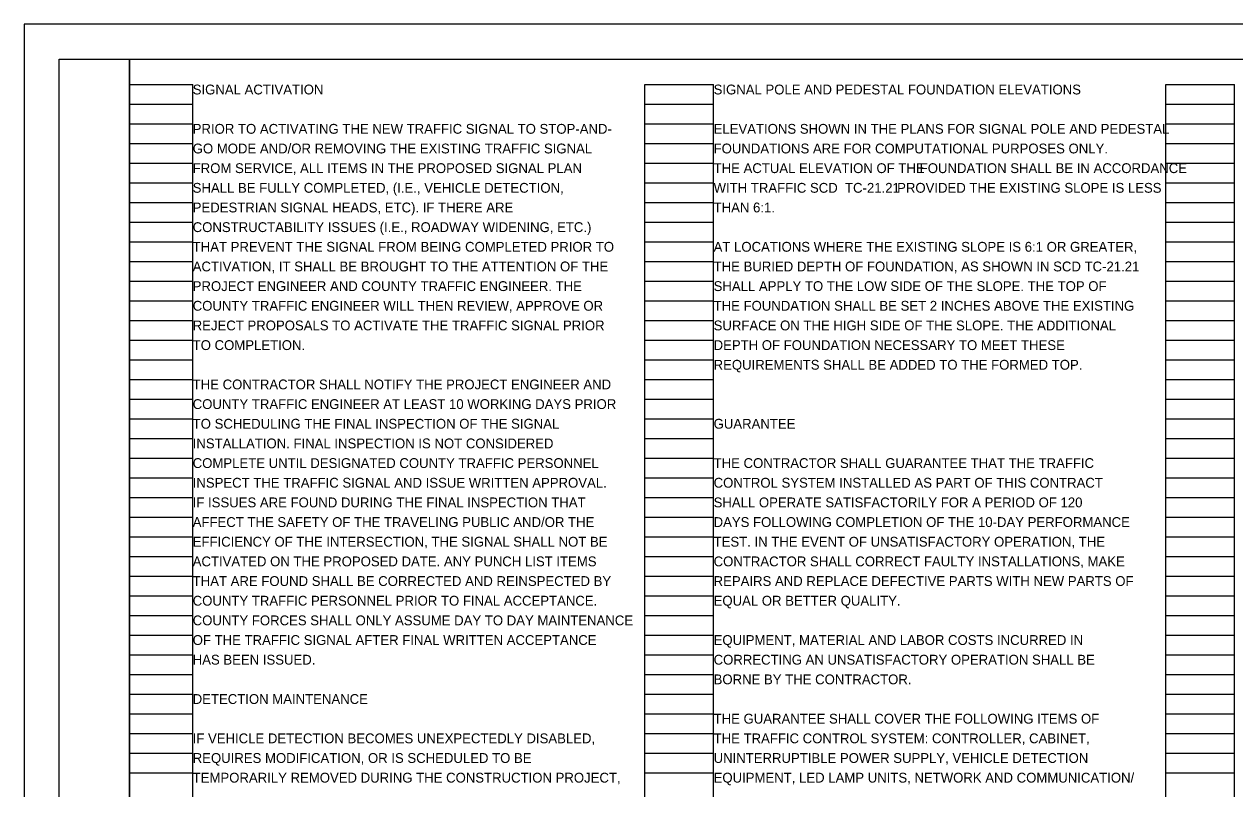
# Model space of a CAD drawing. Extents: x 0 to 34, y 0 to 22.
# Drawn here: x 0 to 17.24, y 11.11 to 22 of the extents above; entities that cross this region are included whole.
import ezdxf

# ---------------------------------------------------------------- set-up
doc = ezdxf.new("R2010")
doc.units = 0
for name, color, linetype in [('SH_Border', 7, 'Continuous'), ('SH_Cut_Line', 7, 'Continuous'), ('SH_Data', 7, 'Continuous'), ('SH_Text', 7, 'Continuous')]:
    doc.layers.add(name, color=color, linetype=linetype)

msp = doc.modelspace()

# ---------------------------------------------------------------- linework, layer by layer
at = {"layer": 'SH_Border'}
for points in [[(0.5, 21.5), (1.5, 21.5), (1.5, 0.5), (0.5, 0.5)], [(1.5, 21.5), (33.5, 21.5), (33.5, 0.5), (1.5, 0.5)]]:
    msp.add_lwpolyline(points, close=True, dxfattribs=at)
at = {"layer": 'SH_Cut_Line'}
msp.add_lwpolyline([(0, 0), (34, 0), (34, 22), (0, 22)], close=True, dxfattribs=at)
at = {"layer": 'SH_Data'}
for p, q in [((1.5, 0.98), (1.5, 21.14)), ((1.5, 21.14), (2.4, 21.14)), ((2.4, 0.98), (2.4, 21.14)), ((8.84, 0.98), (8.84, 21.14)), ((8.84, 21.14), (9.82, 21.14)), ((9.82, 0.98), (9.82, 21.14)), ((16.26, 0.98), (16.26, 21.14)), ((16.26, 21.14), (17.24, 21.14)), ((17.24, 0.98), (17.24, 21.14)), ((1.5, 20.86), (2.4, 20.86)), ((8.84, 20.86), (9.82, 20.86)), ((16.26, 20.86), (17.24, 20.86)), ((1.5, 20.58), (2.4, 20.58)), ((8.84, 20.58), (9.82, 20.58)), ((16.26, 20.58), (17.24, 20.58)), ((1.5, 20.3), (2.4, 20.3)), ((8.84, 20.3), (9.82, 20.3)), ((16.26, 20.3), (17.24, 20.3)), ((1.5, 20.02), (2.4, 20.02)), ((8.84, 20.02), (9.82, 20.02)), ((16.26, 20.02), (17.24, 20.02)), ((1.5, 19.74), (2.4, 19.74)), ((8.84, 19.74), (9.82, 19.74)), ((16.26, 19.74), (17.24, 19.74)), ((1.5, 19.46), (2.4, 19.46)), ((8.84, 19.46), (9.82, 19.46)), ((16.26, 19.46), (17.24, 19.46)), ((1.5, 19.18), (2.4, 19.18)), ((8.84, 19.18), (9.82, 19.18)), ((16.26, 19.18), (17.24, 19.18)), ((1.5, 18.9), (2.4, 18.9)), ((8.84, 18.9), (9.82, 18.9)), ((16.26, 18.9), (17.24, 18.9)), ((1.5, 18.62), (2.4, 18.62)), ((8.84, 18.62), (9.82, 18.62)), ((16.26, 18.62), (17.24, 18.62)), ((1.5, 18.34), (2.4, 18.34)), ((8.84, 18.34), (9.82, 18.34)), ((16.26, 18.34), (17.24, 18.34)), ((1.5, 18.06), (2.4, 18.06)), ((8.84, 18.06), (9.82, 18.06)), ((16.26, 18.06), (17.24, 18.06)), ((1.5, 17.78), (2.4, 17.78)), ((8.84, 17.78), (9.82, 17.78)), ((16.26, 17.78), (17.24, 17.78)), ((1.5, 17.5), (2.4, 17.5)), ((8.84, 17.5), (9.82, 17.5)), ((16.26, 17.5), (17.24, 17.5)), ((1.5, 17.22), (2.4, 17.22)), ((8.84, 17.22), (9.82, 17.22)), ((16.26, 17.22), (17.24, 17.22)), ((1.5, 16.94), (2.4, 16.94)), ((8.84, 16.94), (9.82, 16.94)), ((16.26, 16.94), (17.24, 16.94)), ((1.5, 16.66), (2.4, 16.66)), ((8.84, 16.66), (9.82, 16.66)), ((16.26, 16.66), (17.24, 16.66)), ((1.5, 16.38), (2.4, 16.38)), ((8.84, 16.38), (9.82, 16.38)), ((16.26, 16.38), (17.24, 16.38)), ((1.5, 16.1), (2.4, 16.1)), ((8.84, 16.1), (9.82, 16.1)), ((16.26, 16.1), (17.24, 16.1)), ((1.5, 15.82), (2.4, 15.82)), ((8.84, 15.82), (9.82, 15.82)), ((16.26, 15.82), (17.24, 15.82)), ((1.5, 15.54), (2.4, 15.54)), ((8.84, 15.54), (9.82, 15.54)), ((16.26, 15.54), (17.24, 15.54)), ((1.5, 15.26), (2.4, 15.26)), ((8.84, 15.26), (9.82, 15.26)), ((16.26, 15.26), (17.24, 15.26)), ((1.5, 14.98), (2.4, 14.98)), ((8.84, 14.98), (9.82, 14.98)), ((16.26, 14.98), (17.24, 14.98)), ((1.5, 14.7), (2.4, 14.7)), ((8.84, 14.7), (9.82, 14.7)), ((16.26, 14.7), (17.24, 14.7)), ((1.5, 14.42), (2.4, 14.42)), ((8.84, 14.42), (9.82, 14.42)), ((16.26, 14.42), (17.24, 14.42)), ((1.5, 14.14), (2.4, 14.14)), ((8.84, 14.14), (9.82, 14.14)), ((16.26, 14.14), (17.24, 14.14)), ((1.5, 13.86), (2.4, 13.86)), ((8.84, 13.86), (9.82, 13.86)), ((16.26, 13.86), (17.24, 13.86)), ((1.5, 13.58), (2.4, 13.58)), ((8.84, 13.58), (9.82, 13.58)), ((16.26, 13.58), (17.24, 13.58)), ((1.5, 13.3), (2.4, 13.3)), ((8.84, 13.3), (9.82, 13.3)), ((16.26, 13.3), (17.24, 13.3)), ((1.5, 13.02), (2.4, 13.02)), ((8.84, 13.02), (9.82, 13.02)), ((16.26, 13.02), (17.24, 13.02)), ((1.5, 12.74), (2.4, 12.74)), ((8.84, 12.74), (9.82, 12.74)), ((16.26, 12.74), (17.24, 12.74)), ((1.5, 12.46), (2.4, 12.46)), ((8.84, 12.46), (9.82, 12.46)), ((16.26, 12.46), (17.24, 12.46)), ((1.5, 12.18), (2.4, 12.18)), ((8.84, 12.18), (9.82, 12.18)), ((16.26, 12.18), (17.24, 12.18)), ((1.5, 11.9), (2.4, 11.9)), ((8.84, 11.9), (9.82, 11.9)), ((16.26, 11.9), (17.24, 11.9)), ((1.5, 11.62), (2.4, 11.62)), ((8.84, 11.62), (9.82, 11.62)), ((16.26, 11.62), (17.24, 11.62)), ((1.5, 11.34), (2.4, 11.34)), ((8.84, 11.34), (9.82, 11.34)), ((16.26, 11.34), (17.24, 11.34))]:
    msp.add_line(p, q, dxfattribs=at)

# ---------------------------------------------------------------- texts
at = {"layer": 'SH_Text'}
for s, p in [('SIGNAL ACTIVATION', (2.4, 21)), ('SIGNAL POLE AND PEDESTAL FOUNDATION ELEVATIONS', (9.82, 21)), ('PRIOR TO ACTIVATING THE NEW TRAFFIC SIGNAL TO STOP-AND-', (2.4, 20.44)), ('ELEVATIONS SHOWN IN THE PLANS FOR SIGNAL POLE AND PEDESTAL', (9.82, 20.44)), ('GO MODE AND/OR REMOVING THE EXISTING TRAFFIC SIGNAL', (2.4, 20.16)), ('FOUNDATIONS ARE FOR COMPUTATIONAL PURPOSES ONLY. ', (9.82, 20.16)), ('FROM SERVICE, ALL ITEMS IN THE PROPOSED SIGNAL PLAN', (2.4, 19.88)), ('THE ACTUAL ELEVATION OF THE  ', (9.82, 19.88)), ('FOUNDATION SHALL BE IN ACCORDANCE ', (12.756, 19.88)), ('SHALL BE FULLY COMPLETED, (I.E., VEHICLE DETECTION,', (2.4, 19.6)), ('WITH TRAFFIC SCD  TC-21.21 ', (9.82, 19.6)), ('PROVIDED THE EXISTING SLOPE IS LESS ', (12.434, 19.6)), ('PEDESTRIAN SIGNAL HEADS, ETC). IF THERE ARE', (2.4, 19.32)), ('THAN 6:1.', (9.82, 19.32)), ('CONSTRUCTABILITY ISSUES (I.E., ROADWAY WIDENING, ETC.)', (2.4, 19.04)), ('THAT PREVENT THE SIGNAL FROM BEING COMPLETED PRIOR TO', (2.4, 18.76)), ('AT LOCATIONS WHERE THE EXISTING SLOPE IS 6:1 OR GREATER,', (9.82, 18.76)), ('ACTIVATION, IT SHALL BE BROUGHT TO THE ATTENTION OF THE', (2.4, 18.48)), ('THE BURIED DEPTH OF FOUNDATION, AS SHOWN IN SCD TC-21.21', (9.82, 18.48)), ('PROJECT ENGINEER AND COUNTY TRAFFIC ENGINEER. THE', (2.4, 18.2)), ('SHALL APPLY TO THE LOW SIDE OF THE SLOPE. THE TOP OF', (9.82, 18.2)), ('COUNTY TRAFFIC ENGINEER WILL THEN REVIEW, APPROVE OR', (2.4, 17.92)), ('THE FOUNDATION SHALL BE SET 2 INCHES ABOVE THE EXISTING', (9.82, 17.92)), ('REJECT PROPOSALS TO ACTIVATE THE TRAFFIC SIGNAL PRIOR', (2.4, 17.64)), ('SURFACE ON THE HIGH SIDE OF THE SLOPE. THE ADDITIONAL', (9.82, 17.64)), ('TO COMPLETION.', (2.4, 17.36)), ('DEPTH OF FOUNDATION NECESSARY TO MEET THESE', (9.82, 17.36)), ('REQUIREMENTS SHALL BE ADDED TO THE FORMED TOP.', (9.82, 17.08)), ('THE CONTRACTOR SHALL NOTIFY THE PROJECT ENGINEER AND', (2.4, 16.8)), ('COUNTY TRAFFIC ENGINEER AT LEAST 10 WORKING DAYS PRIOR', (2.4, 16.52)), ('TO SCHEDULING THE FINAL INSPECTION OF THE SIGNAL', (2.4, 16.24)), ('GUARANTEE', (9.82, 16.24)), ('INSTALLATION. FINAL INSPECTION IS NOT CONSIDERED', (2.4, 15.96)), ('COMPLETE UNTIL DESIGNATED COUNTY TRAFFIC PERSONNEL', (2.4, 15.68)), ('THE CONTRACTOR SHALL GUARANTEE THAT THE TRAFFIC', (9.82, 15.68)), ('INSPECT THE TRAFFIC SIGNAL AND ISSUE WRITTEN APPROVAL.', (2.4, 15.4)), ('CONTROL SYSTEM INSTALLED AS PART OF THIS CONTRACT', (9.82, 15.4)), ('IF ISSUES ARE FOUND DURING THE FINAL INSPECTION THAT', (2.4, 15.12)), ('SHALL OPERATE SATISFACTORILY FOR A PERIOD OF 120', (9.82, 15.12)), ('AFFECT THE SAFETY OF THE TRAVELING PUBLIC AND/OR THE', (2.4, 14.84)), ('DAYS FOLLOWING COMPLETION OF THE 10-DAY PERFORMANCE', (9.82, 14.84)), ('EFFICIENCY OF THE INTERSECTION, THE SIGNAL SHALL NOT BE', (2.4, 14.56)), ('TEST. IN THE EVENT OF UNSATISFACTORY OPERATION, THE', (9.82, 14.56)), ('ACTIVATED ON THE PROPOSED DATE. ANY PUNCH LIST ITEMS', (2.4, 14.28)), ('CONTRACTOR SHALL CORRECT FAULTY INSTALLATIONS, MAKE', (9.82, 14.28)), ('THAT ARE FOUND SHALL BE CORRECTED AND REINSPECTED BY', (2.4, 14)), ('REPAIRS AND REPLACE DEFECTIVE PARTS WITH NEW PARTS OF', (9.82, 14)), ('COUNTY TRAFFIC PERSONNEL PRIOR TO FINAL ACCEPTANCE.', (2.4, 13.72)), ('EQUAL OR BETTER QUALITY.', (9.82, 13.72)), ('COUNTY FORCES SHALL ONLY ASSUME DAY TO DAY MAINTENANCE', (2.4, 13.44)), ('OF THE TRAFFIC SIGNAL AFTER FINAL WRITTEN ACCEPTANCE', (2.4, 13.16)), ('EQUIPMENT, MATERIAL AND LABOR COSTS INCURRED IN', (9.82, 13.16)), ('HAS BEEN ISSUED.', (2.4, 12.88)), ('CORRECTING AN UNSATISFACTORY OPERATION SHALL BE', (9.82, 12.88)), ('BORNE BY THE CONTRACTOR.', (9.82, 12.6)), ('DETECTION MAINTENANCE', (2.4, 12.32)), ('THE GUARANTEE SHALL COVER THE FOLLOWING ITEMS OF', (9.82, 12.04)), ('IF VEHICLE DETECTION BECOMES UNEXPECTEDLY DISABLED,', (2.4, 11.76)), ('THE TRAFFIC CONTROL SYSTEM: CONTROLLER, CABINET,', (9.82, 11.76)), ('REQUIRES MODIFICATION, OR IS SCHEDULED TO BE', (2.4, 11.48)), ('UNINTERRUPTIBLE POWER SUPPLY, VEHICLE DETECTION', (9.82, 11.48)), ('TEMPORARILY REMOVED DURING THE CONSTRUCTION PROJECT,', (2.4, 11.2)), ('EQUIPMENT, LED LAMP UNITS, NETWORK AND COMMUNICATION/', (9.82, 11.2))]:
    msp.add_text(s, height=0.14, dxfattribs=at).set_placement(p)

doc.saveas('drawing.dxf')
